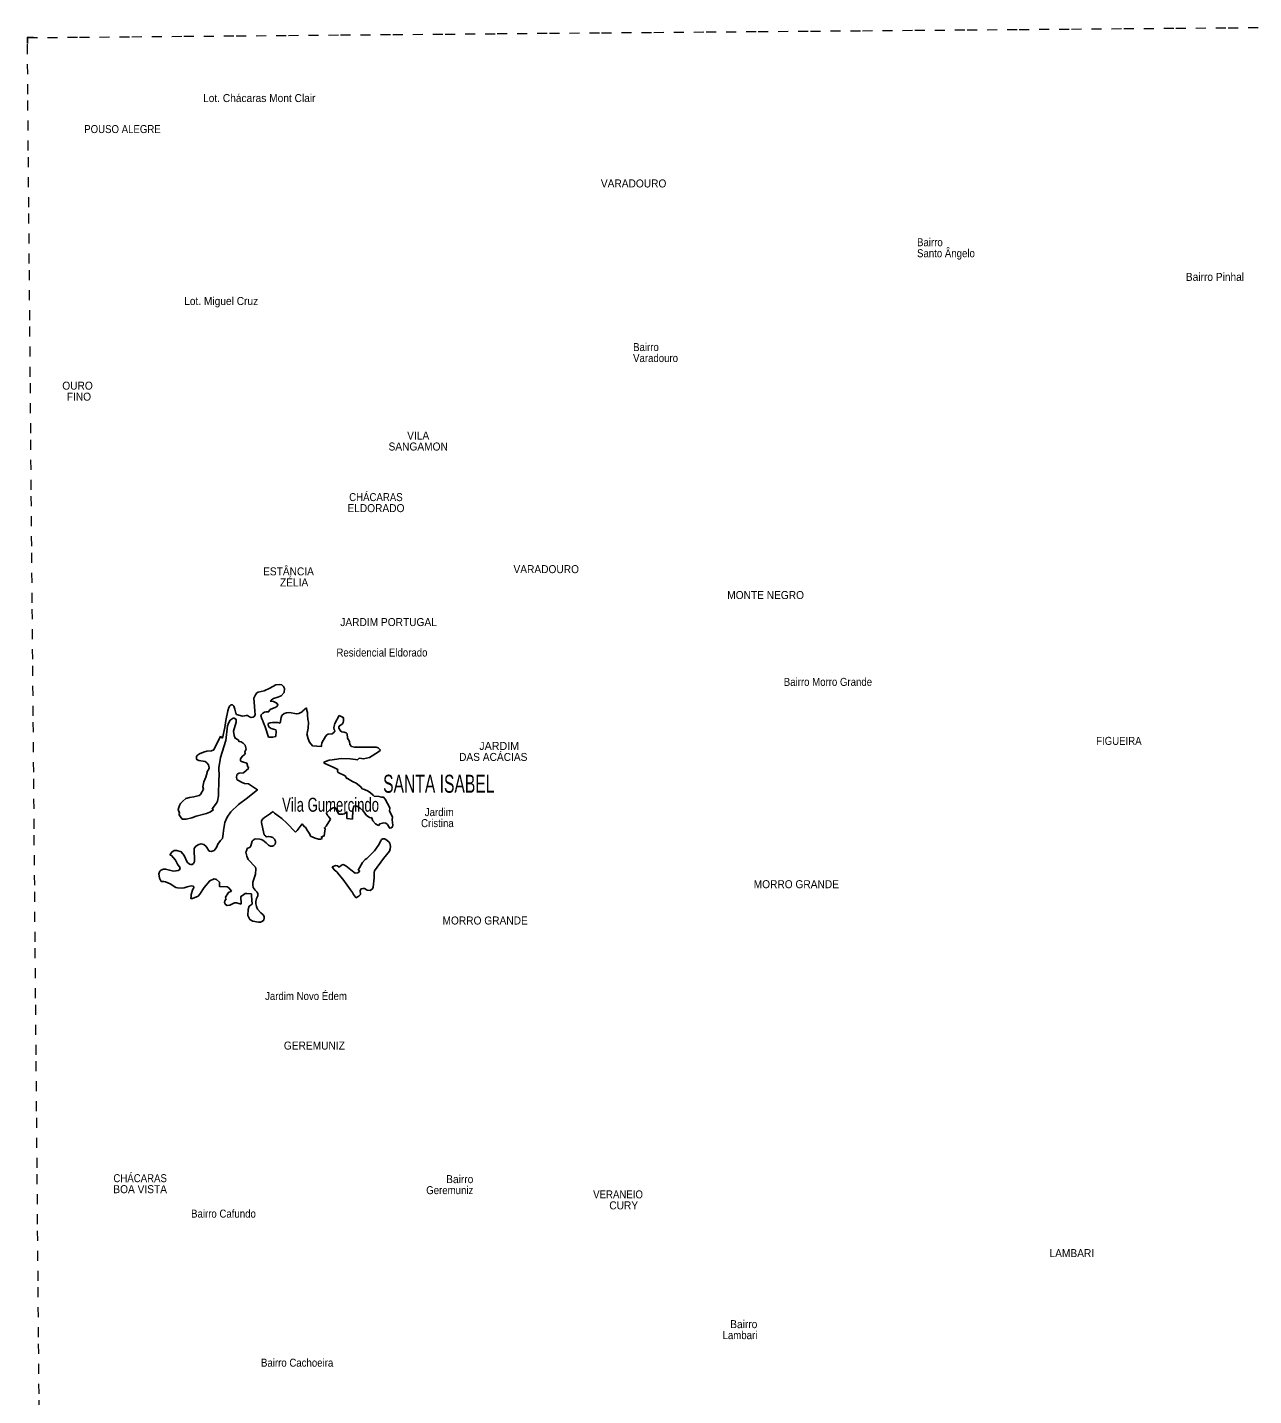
# Model space of a CAD drawing. Extents: x 372.1 to 397.9, y 7400.6 to 7428.4.
# Drawn here: x 372.13 to 384.39, y 7414.67 to 7428.35 of the extents above; entities that cross this region are included whole.
import ezdxf
from ezdxf.enums import TextEntityAlignment as Align

# ---------------------------------------------------------------- set-up
doc = ezdxf.new("R2010")
doc.units = 0
doc.header["$LTSCALE"] = 0.032
doc.linetypes.add('SHORT_DASHED', pattern=[2.7, 1.5, -1.2])
for name, color, linetype, lineweight in [('41', 7, 'Continuous', 25), ('46', 7, 'SHORT_DASHED', 13), ('63', 7, 'Continuous', 25)]:
    doc.layers.add(name, color=color, linetype=linetype, lineweight=lineweight)
doc.layers.add('61', color=7, linetype='Continuous')

msp = doc.modelspace()

# ---------------------------------------------------------------- linework, layer by layer
at = {"layer": '41'}
for points in [[(374.2202, 7421.4783), (374.2786, 7421.4631), (374.3175, 7421.4697), (374.3303, 7421.4688), (374.3502, 7421.4537), (374.3654, 7421.4495), (374.386, 7421.4505), (374.3968, 7421.4579), (374.4066, 7421.4747), (374.4016, 7421.5165), (374.3979, 7421.5578), (374.3918, 7421.6431), (374.4078, 7421.6766), (374.4207, 7421.6935), (374.4354, 7421.7011)], [(374.4354, 7421.7011), (374.4949, 7421.7136), (374.5533, 7421.7416), (374.6118, 7421.7752), (374.6506, 7421.7799)], [(374.6506, 7421.7799), (374.6735, 7421.7735), (374.6887, 7421.7577), (374.6984, 7421.7377), (374.6963, 7421.6999), (374.6637, 7421.6662), (374.6333, 7421.6525), (374.5884, 7421.6383), (374.5672, 7421.6241), (374.5569, 7421.6112)], [(374.0773, 7421.2414), (374.1017, 7421.3474), (374.1129, 7421.4193), (374.1329, 7421.5152), (374.1424, 7421.5492), (374.1508, 7421.5639), (374.1614, 7421.5744), (374.1802, 7421.5744), (374.1908, 7421.5618), (374.2023, 7421.5324), (374.2107, 7421.4904), (374.2202, 7421.4783)], [(374.5569, 7421.6112), (374.5895, 7421.607), (374.6094, 7421.5975), (374.6252, 7421.5881), (374.6304, 7421.5734), (374.6231, 7421.5597), (374.6126, 7421.5513), (374.5569, 7421.5272), (374.5433, 7421.5125), (374.5405, 7421.5043)], [(374.8759, 7421.5052), (374.8833, 7421.5149), (374.897, 7421.5286), (374.9198, 7421.5439)], [(374.9198, 7421.5439), (374.9208, 7421.5182), (374.9271, 7421.4993), (374.9302, 7421.4752), (374.9313, 7421.4279), (374.9386, 7421.4006), (374.9365, 7421.3424), (374.9256, 7421.2915), (374.9226, 7421.2844)], [(374.236, 7421.2267), (374.2057, 7421.2407), (374.1945, 7421.269), (374.1903, 7421.3109), (374.2154, 7421.4009), (374.214, 7421.4157), (374.2144, 7421.4233), (374.2128, 7421.4321), (374.1952, 7421.4417), (374.184, 7421.4417), (374.1553, 7421.4217), (374.1417, 7421.4001), (374.1297, 7421.365), (374.1105, 7421.2195), (374.0594, 7421.0485), (374.0414, 7420.9443), (374.044, 7420.8615)], [(374.5405, 7421.5043), (374.5129, 7421.5052), (374.4988, 7421.501), (374.4814, 7421.4905), (374.4663, 7421.4758), (374.4626, 7421.4681)], [(374.4626, 7421.4681), (374.4736, 7421.4349), (374.4813, 7421.4145), (374.4877, 7421.3953), (374.5038, 7421.3568), (374.539, 7421.252)], [(374.5338, 7421.3891), (374.556, 7421.3964), (374.578, 7421.3985), (374.6336, 7421.3985), (374.6568, 7421.3932)], [(374.6115, 7421.3261), (374.5664, 7421.3387), (374.5464, 7421.3513), (374.5359, 7421.3723), (374.5338, 7421.3891)], [(374.6568, 7421.3932), (374.6637, 7421.4495), (374.6735, 7421.4674), (374.6938, 7421.4888), (374.7194, 7421.496), (374.745, 7421.4968), (374.8217, 7421.484), (374.8406, 7421.4884), (374.8759, 7421.5052)], [(375.2036, 7421.3112), (375.198, 7421.3258), (375.1956, 7421.3258), (375.1933, 7421.3482), (375.2018, 7421.3896), (375.2458, 7421.4673)], [(375.2458, 7421.4673), (375.2867, 7421.4473), (375.2899, 7421.4369), (375.2899, 7421.4145), (375.2867, 7421.4001), (375.2772, 7421.385), (375.2452, 7421.3602), (375.2412, 7421.3506), (375.242, 7421.3402), (375.2586, 7421.3135), (375.2716, 7421.3049), (375.2968, 7421.3017), (375.3147, 7421.2946), (375.3244, 7421.2836), (375.3285, 7421.2403), (375.348, 7421.2072), (375.3523, 7421.1788), (375.3698, 7421.1588), (375.3986, 7421.1508), (375.6153, 7421.152), (375.634, 7421.1465), (375.6568, 7421.126), (375.6581, 7421.1209)], [(373.9931, 7421.1247), (374.0075, 7421.1629), (374.0531, 7421.2462), (374.0575, 7421.2613)], [(374.0575, 7421.2613), (374.0645, 7421.251), (374.0773, 7421.2414)], [(374.539, 7421.252), (374.5818, 7421.2504), (374.6118, 7421.2598)], [(374.6118, 7421.2598), (374.6144, 7421.3119), (374.6115, 7421.3261)], [(374.9226, 7421.2844), (374.9361, 7421.2341), (374.9498, 7421.2032), (374.9783, 7421.1652), (375.0644, 7421.1571), (375.0677, 7421.1698)], [(375.0677, 7421.1698), (375.0719, 7421.1957), (375.1072, 7421.2587), (375.1231, 7421.2768), (375.1358, 7421.2827), (375.1748, 7421.2864), (375.1919, 7421.2982), (375.2036, 7421.3112)], [(373.9251, 7420.9093), (373.9397, 7420.9246), (373.9467, 7420.9449), (373.9397, 7420.9746), (373.9219, 7420.9966), (373.9068, 7421.007), (373.842, 7421.019), (373.8237, 7421.027), (373.8181, 7421.0358), (373.8181, 7421.0589), (373.8284, 7421.0717), (373.8476, 7421.0845), (373.89, 7421.1013), (373.9235, 7421.1117), (373.9683, 7421.1157), (373.9931, 7421.1247)], [(374.3031, 7421.1044), (374.3156, 7421.1312), (374.3045, 7421.1731), (374.285, 7421.192), (374.2669, 7421.2042), (374.2443, 7421.2077), (374.236, 7421.2267)], [(374.3216, 7420.9919), (374.2794, 7421.0044), (374.2669, 7421.0098), (374.2572, 7421.0192), (374.2572, 7421.0354), (374.2739, 7421.0597), (374.2989, 7421.0786), (374.3042, 7421.0875), (374.3031, 7421.1044)], [(375.6581, 7421.1209), (375.6372, 7421.104), (375.5501, 7421.0494), (375.4892, 7421.0363), (375.4693, 7421.0373), (375.4466, 7421.0404), (375.4273, 7421.0268), (375.4082, 7421.0273), (375.3559, 7421.0352)], [(374.3418, 7420.9426), (374.3335, 7420.9567), (374.3216, 7420.9919)], [(375.3559, 7421.0352), (375.2668, 7421.0374), (375.1981, 7421.0302), (375.175, 7421.0244), (375.1456, 7421.0223), (375.091, 7421.0034)], [(375.091, 7421.0034), (375.096, 7420.9933), (375.1934, 7420.9473), (375.2306, 7420.9277)], [(373.8819, 7420.7537), (373.8934, 7420.8046), (373.9123, 7420.8536), (373.9243, 7420.8984), (373.9251, 7420.9093)], [(374.044, 7420.8615), (374.0408, 7420.8321), (374.0378, 7420.6646), (374.0272, 7420.6132)], [(374.2214, 7420.8301), (374.2196, 7420.8558), (374.2266, 7420.8815), (374.2456, 7420.8927), (374.2894, 7420.8944), (374.3418, 7420.9426)], [(374.2739, 7420.7978), (374.2321, 7420.8214), (374.2214, 7420.8301)], [(375.2306, 7420.9277), (375.2301, 7420.913), (375.2353, 7420.897), (375.3051, 7420.8648), (375.3227, 7420.8381), (375.3289, 7420.8371)], [(375.3289, 7420.8371), (375.3785, 7420.8073), (375.3819, 7420.8063), (375.3849, 7420.8041)], [(373.6475, 7420.4922), (373.6348, 7420.5271), (373.6487, 7420.5689), (373.6585, 7420.5878), (373.6807, 7420.6121), (373.7114, 7420.6378), (373.749, 7420.6499), (373.7907, 7420.6553), (373.846, 7420.669), (373.8572, 7420.6786), (373.8899, 7420.7305), (373.8819, 7420.7537)], [(374.1266, 7420.4513), (374.1637, 7420.5041), (374.24, 7420.5779), (374.3288, 7420.6446), (374.4002, 7420.7034), (374.4286, 7420.7254), (374.3394, 7420.7865)], [(374.3394, 7420.7865), (374.3002, 7420.7883), (374.2739, 7420.7978)], [(375.3849, 7420.8041), (375.4162, 7420.7904), (375.4621, 7420.7538), (375.4742, 7420.7363)], [(375.4742, 7420.7363), (375.4977, 7420.7297), (375.5345, 7420.7105), (375.56, 7420.6945), (375.5842, 7420.6713), (375.5953, 7420.6632)], [(374.0272, 7420.6132), (374.0181, 7420.5906), (373.9754, 7420.5359), (373.988, 7420.5243)], [(375.3917, 7420.5647), (375.3833, 7420.5206), (375.3784, 7420.4322), (375.3228, 7420.4395), (375.3234, 7420.5069)], [(375.4452, 7420.5479), (375.423, 7420.5615), (375.3917, 7420.5647)], [(375.5953, 7420.6632), (375.6435, 7420.6589), (375.6688, 7420.6513), (375.6897, 7420.6505), (375.7045, 7420.6327), (375.7512, 7420.5462), (375.748, 7420.5104), (375.7792, 7420.4569)], [(373.6598, 7420.4556), (373.6439, 7420.4764), (373.6439, 7420.4812), (373.6475, 7420.4922)], [(373.988, 7420.5243), (373.9523, 7420.5028), (373.9172, 7420.4884), (373.8165, 7420.462), (373.7717, 7420.446), (373.7158, 7420.4333), (373.6934, 7420.4309), (373.6758, 7420.4333), (373.6598, 7420.4556)], [(374.0871, 7420.2842), (374.0892, 7420.3178), (374.1018, 7420.3986), (374.1266, 7420.4513)], [(374.5816, 7420.5083), (374.5579, 7420.4875), (374.4973, 7420.45), (374.4813, 7420.4349), (374.4693, 7420.4141), (374.4671, 7420.3998), (374.4835, 7420.3358), (374.4943, 7420.2759)], [(374.8074, 7420.3011), (374.7213, 7420.3929), (374.6715, 7420.4388), (374.5971, 7420.4936), (374.5816, 7420.5083)], [(375.1586, 7420.4306), (375.1149, 7420.3613), (375.0981, 7420.3464), (375.1046, 7420.3346), (375.096, 7420.2639), (375.0675, 7420.2568), (375.075, 7420.2392)], [(375.2046, 7420.5496), (375.1843, 7420.5439), (375.1562, 7420.53), (375.1142, 7420.4923)], [(375.1142, 7420.4923), (375.1245, 7420.478), (375.1325, 7420.4668), (375.1421, 7420.454), (375.1586, 7420.4306)], [(375.2405, 7420.4835), (375.2276, 7420.5052), (375.2046, 7420.5496)], [(375.3234, 7420.5069), (375.2952, 7420.4869), (375.2809, 7420.4819), (375.2615, 7420.4805), (375.2405, 7420.4835)], [(375.568, 7420.4489), (375.556, 7420.4468), (375.5439, 7420.4516), (375.5187, 7420.4699), (375.4841, 7420.5156), (375.4569, 7420.5419), (375.4452, 7420.5479)], [(375.6431, 7420.3701), (375.6334, 7420.3726), (375.608, 7420.3853), (375.5824, 7420.4165), (375.568, 7420.4489)], [(375.7792, 7420.4569), (375.7766, 7420.4268), (375.7814, 7420.3717), (375.7774, 7420.3542), (375.7662, 7420.3438), (375.755, 7420.3414), (375.747, 7420.3438), (375.7278, 7420.3789), (375.7134, 7420.3933), (375.6911, 7420.3949), (375.6519, 7420.3861), (375.6431, 7420.3701)], [(373.5527, 7420.075), (373.5707, 7420.1026), (373.5944, 7420.1188), (373.6236, 7420.1202), (373.6668, 7420.104), (373.6966, 7420.0681), (373.7239, 7420.0014), (373.7493, 7419.9826), (373.7605, 7419.9786), (373.7765, 7419.9794), (373.7877, 7419.9882), (373.799, 7420.0095), (373.7962, 7420.1391), (373.8129, 7420.1607), (373.8436, 7420.1796), (373.8645, 7420.1864), (373.8909, 7420.1796), (373.9146, 7420.158), (373.9466, 7420.1134), (373.9661, 7420.1094), (373.9939, 7420.1202), (374.019, 7420.1499), (374.0329, 7420.181), (374.0593, 7420.2201), (374.0794, 7420.2404), (374.0871, 7420.2842)], [(374.8745, 7420.3866), (374.8266, 7420.3175), (374.8074, 7420.3011)], [(374.911, 7420.3474), (374.8992, 7420.3541), (374.8862, 7420.372), (374.8745, 7420.3866)], [(374.9516, 7420.2815), (374.9383, 7420.3014), (374.9323, 7420.3112), (374.9235, 7420.3255), (374.911, 7420.3474)], [(375.075, 7420.2392), (375.0571, 7420.2332), (375.0382, 7420.2317), (375.0065, 7420.2406), (374.9588, 7420.2623), (374.9516, 7420.2815)], [(374.5175, 7420.2546), (374.537, 7420.2596), (374.5636, 7420.2551), (374.5804, 7420.2479), (374.598, 7420.2319), (374.6083, 7420.2127), (374.6099, 7420.1991), (374.6038, 7420.1834), (374.5933, 7420.1693), (374.5773, 7420.1632), (374.5592, 7420.1632), (374.5377, 7420.1733), (374.5156, 7420.1951), (374.4805, 7420.2207), (374.4653, 7420.228), (374.4514, 7420.2328), (374.4048, 7420.2355), (374.3846, 7420.2231), (374.3766, 7420.2135), (374.3622, 7420.1664), (374.3542, 7420.1512), (374.3259, 7420.1388)], [(374.4943, 7420.2759), (374.5104, 7420.2617), (374.5122, 7420.2601), (374.5175, 7420.2546)], [(375.662, 7420.2166), (375.6702, 7420.2288), (375.6831, 7420.2359), (375.6991, 7420.2367), (375.711, 7420.2303), (375.7422, 7420.2039), (375.7518, 7420.1919), (375.758, 7420.1593), (375.7554, 7420.1349), (375.7477, 7420.1136), (375.6876, 7420.0385), (375.6, 7419.9147), (375.5952, 7419.8979), (375.5952, 7419.8468), (375.5855, 7419.7536), (375.5776, 7419.7349), (375.5552, 7419.7197), (375.5265, 7419.7237), (375.4985, 7419.7397), (375.4833, 7419.7405), (375.4649, 7419.7341), (375.4545, 7419.7189), (375.4585, 7419.6781), (375.4418, 7419.6606), (375.4128, 7419.6449)], [(375.4365, 7419.9236), (375.4801, 7419.9978), (375.5054, 7420.0287), (375.5211, 7420.0403), (375.5984, 7420.116), (375.6399, 7420.172), (375.662, 7420.2166)], [(373.6564, 7419.9455), (373.6301, 7419.9822), (373.6091, 7420.0211), (373.5704, 7420.0689), (373.5527, 7420.075)], [(374.3259, 7420.1388), (374.32, 7420.1146), (374.3159, 7420.1104), (374.3129, 7420.1019)], [(374.3129, 7420.1019), (374.322, 7420.0622), (374.3366, 7420.0284), (374.4075, 7419.9509), (374.4117, 7419.935), (374.4082, 7419.8823), (374.3822, 7419.8036), (374.3806, 7419.7748), (374.3854, 7419.7493), (374.4038, 7419.7237), (374.4243, 7419.7029), (374.4333, 7419.6853), (374.4326, 7419.6671), (374.418, 7419.6374), (374.411, 7419.6102), (374.411, 7419.5847), (374.4174, 7419.5591), (374.4301, 7419.5335), (374.4613, 7419.496), (374.4863, 7419.4748), (374.4946, 7419.4586), (374.4967, 7419.4451), (374.4925, 7419.4236), (374.4779, 7419.4107), (374.4598, 7419.404), (374.4376, 7419.4026), (374.3826, 7419.4114), (374.3534, 7419.4303), (374.3335, 7419.4696), (374.3346, 7419.5288), (374.3457, 7419.5612), (374.375, 7419.5816)], [(373.4649, 7419.8084), (373.4502, 7419.8418), (373.4433, 7419.8859), (373.4531, 7419.912), (373.4617, 7419.9235), (373.4873, 7419.9307), (373.5096, 7419.933), (373.5882, 7419.9135), (373.6132, 7419.9149), (373.6347, 7419.9196), (373.6481, 7419.9262), (373.6564, 7419.9455)], [(375.1745, 7419.9548), (375.2116, 7419.9682), (375.23, 7419.9658), (375.244, 7419.9533)], [(375.4128, 7419.6449), (375.4074, 7419.6518), (375.3895, 7419.6804), (375.3779, 7419.6996), (375.3595, 7419.7261), (375.3238, 7419.7723), (375.2826, 7419.8307), (375.2621, 7419.8562), (375.2437, 7419.8746), (375.2218, 7419.905), (375.1948, 7419.927), (375.1745, 7419.9548)], [(375.244, 7419.9533), (375.2671, 7419.9708), (375.2859, 7419.9778), (375.3114, 7419.967)], [(375.3114, 7419.967), (375.3625, 7419.924), (375.4068, 7419.8937)], [(375.4068, 7419.8937), (375.4318, 7419.8972), (375.4458, 7419.9069), (375.4497, 7419.915), (375.4365, 7419.9236)], [(373.556, 7419.7844), (373.508, 7419.8044), (373.492, 7419.8084), (373.4649, 7419.8084)], [(373.6293, 7419.7461), (373.6126, 7419.7482), (373.556, 7419.7844)], [(373.7894, 7419.7634), (373.7649, 7419.7642), (373.7252, 7419.7568), (373.6967, 7419.746), (373.6716, 7419.7426), (373.6293, 7419.7461)], [(374.0482, 7419.8021), (374.0182, 7419.8273), (373.9945, 7419.8368), (373.9507, 7419.8172), (373.8948, 7419.7493), (373.8532, 7419.6821), (373.8345, 7419.663), (373.7797, 7419.6382), (373.7637, 7419.6382), (373.7669, 7419.6622), (373.7653, 7419.6805), (373.7837, 7419.7326), (373.7935, 7419.7446), (373.7894, 7419.7634)], [(374.1702, 7419.7118), (374.1425, 7419.7453), (374.1265, 7419.7549), (374.0482, 7419.7601), (374.0482, 7419.8021)], [(374.2656, 7419.5824), (374.2185, 7419.5948), (374.1976, 7419.5948), (374.1521, 7419.5735), (374.1249, 7419.5703), (374.1089, 7419.5783), (374.1001, 7419.5974), (374.1037, 7419.615), (374.1155, 7419.6352)], [(374.1155, 7419.6352), (374.1114, 7419.6393), (374.1094, 7419.653), (374.1382, 7419.699), (374.1702, 7419.7118)], [(374.3686, 7419.6858), (374.3207, 7419.6904), (374.3068, 7419.6878), (374.2776, 7419.6702), (374.2637, 7419.659), (374.2634, 7419.655), (374.2616, 7419.6341)], [(374.2616, 7419.6341), (374.266, 7419.6069), (374.2656, 7419.5824)], [(374.375, 7419.5816), (374.3678, 7419.6688), (374.3686, 7419.6858)]]:
    msp.add_lwpolyline(points, dxfattribs=at)
at = {"layer": '46'}
for points in [[(372.1277, 7428.2453), (372.6497, 7428.2497), (373.1716, 7428.2542), (373.6936, 7428.2587), (374.2156, 7428.2631), (374.7376, 7428.2675), (375.2596, 7428.2719), (375.7816, 7428.2763), (376.3035, 7428.2806), (376.8255, 7428.285), (377.3475, 7428.2893), (377.8695, 7428.2936), (378.3914, 7428.2979), (378.9134, 7428.3022), (379.4354, 7428.3064), (379.9574, 7428.3106), (380.4793, 7428.3148), (381.0013, 7428.319), (381.5233, 7428.3232), (382.0453, 7428.3274), (382.5672, 7428.3315), (383.0892, 7428.3356), (383.6112, 7428.3397), (384.1332, 7428.3438), (384.6551, 7428.3479)], [(372.2496, 7414.1225), (372.2447, 7414.6874), (372.2399, 7415.2523), (372.235, 7415.8172), (372.2301, 7416.3821), (372.2252, 7416.947), (372.2203, 7417.512), (372.2154, 7418.0769), (372.2105, 7418.6418), (372.2057, 7419.2067), (372.2008, 7419.7716), (372.1959, 7420.3365), (372.191, 7420.9014), (372.1861, 7421.4663), (372.1813, 7422.0313), (372.1764, 7422.5962), (372.1715, 7423.1611), (372.1666, 7423.726), (372.1618, 7424.2909), (372.1569, 7424.8558), (372.152, 7425.4207), (372.1471, 7425.9856), (372.1423, 7426.5505), (372.1374, 7427.1154), (372.1325, 7427.6804), (372.1277, 7428.2453)]]:
    msp.add_lwpolyline(points, dxfattribs=at)
at = {"layer": '63'}
msp.add_lwpolyline([(372.1894, 7428.2467), (372.1278, 7428.2467), (372.1278, 7428.186)], dxfattribs=at)

# ---------------------------------------------------------------- texts
at = {"layer": '61'}
for s, height, width, p in [('Lot. Chácaras Mont Clair', 0.08, 0.95, (373.8845, 7427.6011)), ('Bairro', 0.08, 0.9, (381.0232, 7426.1598)), ('Santo Ângelo', 0.08, 0.9, (381.0232, 7426.0498)), ('Lot. Miguel Cruz', 0.08, 0.95, (373.6957, 7425.5722)), ('Varadouro', 0.08, 0.9, (378.184, 7425.0018)), ('Bairro', 0.08, 0.9, (378.184, 7425.1118)), ('Residencial Eldorado', 0.08, 0.9, (375.2182, 7422.058)), ('Bairro Morro Grande', 0.08, 0.9, (379.6907, 7421.7645)), ('SANTA ISABEL', 0.18, 0.65, (375.6848, 7420.6962)), ('Vila Gumercindo', 0.14, 0.7, (374.6749, 7420.5064)), ('Jardim Novo Édem', 0.08, 0.9, (374.5044, 7418.624)), ('Bairro Cafundo', 0.08, 0.9, (373.7647, 7416.4485))]:
    msp.add_text(s, height=height, dxfattribs=dict(at, width=width)).set_placement(p)
for s, width, p in [('POUSO ALEGRE', 0.9, (373.0788, 7427.2911)), ('VARADOURO', 0.95, (378.1893, 7426.7476)), ('OURO', 0.95, (372.6293, 7424.7259)), (' FINO', 0.95, (372.6292, 7424.6159)), ('VILA', 0.95, (376.0354, 7424.2276)), ('SANGAMON', 0.95, (376.0354, 7424.1176)), ('CHÁCARAS', 0.9, (375.6129, 7423.6118)), ('ELDORADO', 0.95, (375.6128, 7423.5018)), ('ESTÂNCIA', 0.95, (374.7385, 7422.8692)), ('VARADOURO', 0.95, (377.3156, 7422.8917)), ('    ZÉLIA', 0.95, (374.7385, 7422.7592)), ('MONTE NEGRO', 0.95, (379.5091, 7422.6327)), ('JARDIM PORTUGAL', 0.95, (375.7394, 7422.3625)), ('FIGUEIRA', 0.9, (383.0412, 7421.175)), ('DAS ACÁCIAS', 0.95, (376.7858, 7421.0142)), ('MORRO GRANDE', 0.95, (379.8161, 7419.742)), ('MORRO GRANDE', 0.95, (376.7049, 7419.379)), ('GEREMUNIZ', 0.95, (374.9973, 7418.1285)), ('CHÁCARAS', 0.9, (373.2554, 7416.803)), ('BOA VISTA', 0.95, (373.2554, 7416.693)), ('VERANEIO', 0.9, (378.0337, 7416.641)), ('    CURY', 0.95, (378.0337, 7416.531)), ('LAMBARI', 0.95, (382.5707, 7416.0537))]:
    msp.add_text(s, height=0.08, dxfattribs=dict(at, width=width)).set_placement(p, align=Align.CENTER)
for s, width, p in [('Bairro Pinhal', 0.95, (384.2929, 7425.8136)), ('Cristina', 0.9, (376.3904, 7420.3526)), ('Jardim', 0.9, (376.3904, 7420.4626)), ('   Bairro', 0.95, (376.5865, 7416.7933)), ('Geremuniz', 0.9, (376.5865, 7416.6833)), (' Bairro', 0.95, (379.4264, 7415.3436)), ('Lambari', 0.9, (379.4264, 7415.2336)), ('Bairro Cachoeira', 0.9, (375.1862, 7414.9584))]:
    msp.add_text(s, height=0.08, dxfattribs=dict(at, width=width)).set_placement(p, align=Align.RIGHT)
msp.add_text('    JARDIM', height=0.08, dxfattribs=at).set_placement((376.7858, 7421.1242), align=Align.CENTER)

doc.saveas('drawing.dxf')
